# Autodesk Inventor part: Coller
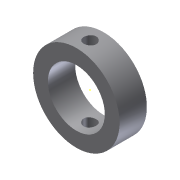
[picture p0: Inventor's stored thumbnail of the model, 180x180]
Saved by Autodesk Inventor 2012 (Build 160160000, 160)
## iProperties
Created: 2011-09
Part Number: Coller
Material: Default
Document SubType Name: Modeling
Designer: CADCIM
Density: 1 g/cm^3
Author: CADCIM
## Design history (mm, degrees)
sketch "Sketch1"
  geometry: 1 further point
sketch "Sketch2"
  geometry: C1 r 12.5 at (0, 0); C2 r 19 at (0, 0); 1 further point
  constraints: 2 centre point, 2 coincident
  dimensions: "d0" = 25 diameter of C1; "d1" = 38 diameter of C2
extrude "Extrusion1" new body sketch "Sketch2" stored distance "d2" = 12; taper "d3" = 0 deg
sketch "Sketch3"
  geometry: C1 r 2.75 at (0, 0); 1 further point
  constraints: 1 centre point, 1 coincident
  dimensions: "d4" = 5.5 diameter of C1
extrude "Extrusion2" cut sketch "Sketch3" stored distance "d5" = 12; taper "d6" = 0 deg
body "Solid1"
